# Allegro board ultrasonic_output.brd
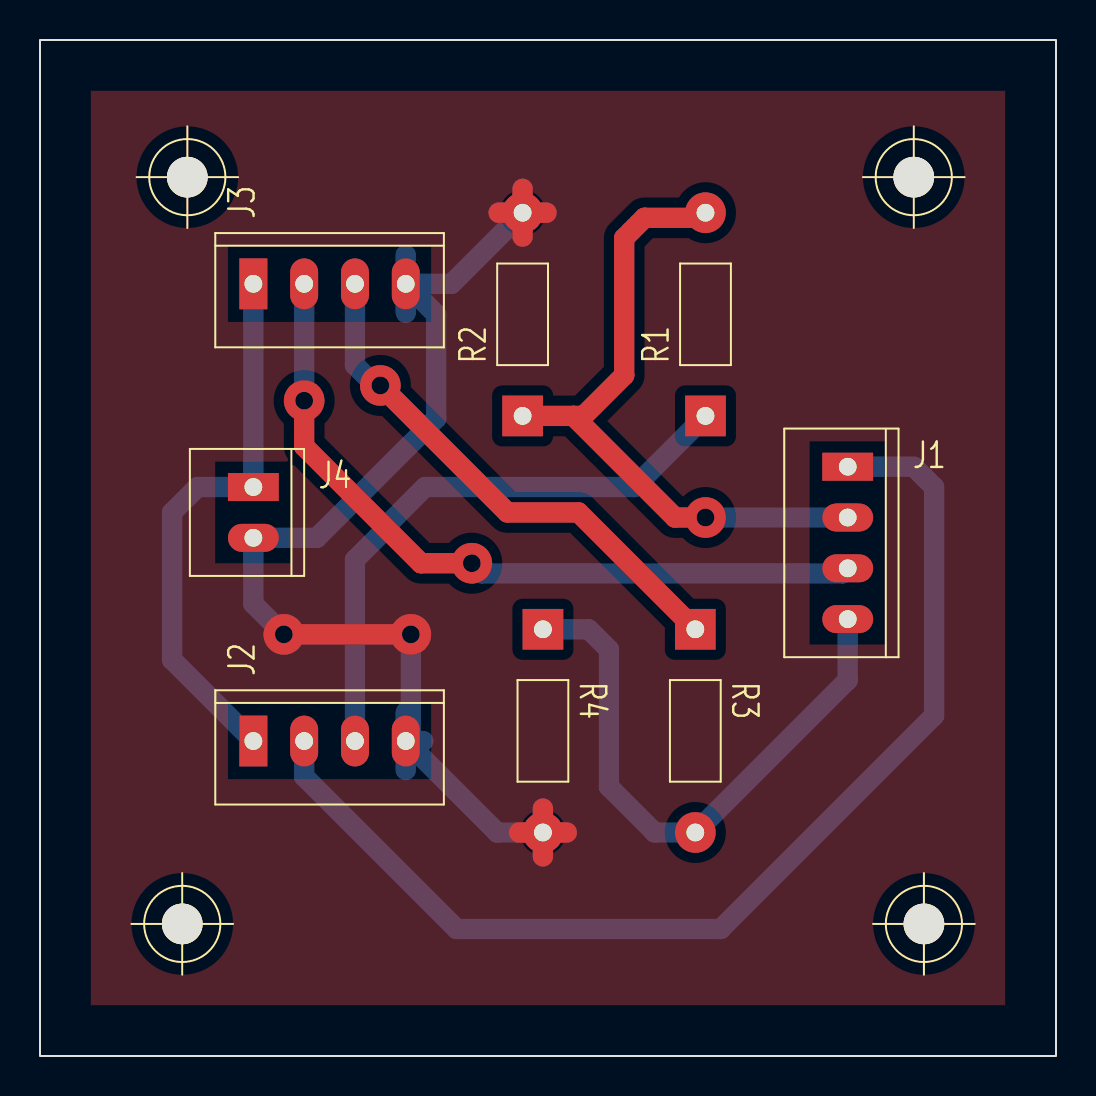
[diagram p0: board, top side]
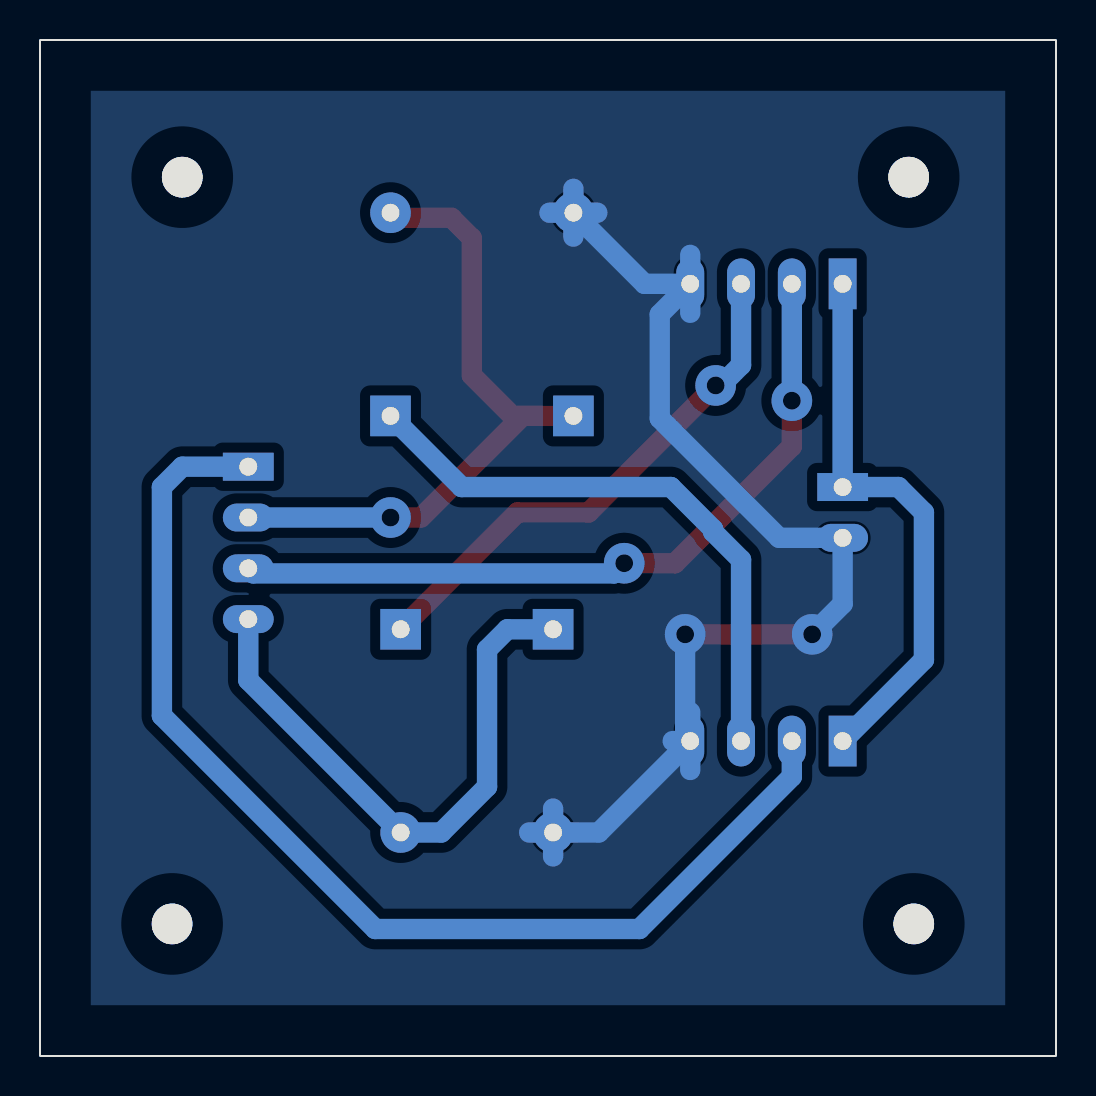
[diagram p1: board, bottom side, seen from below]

Outline 50.8 x 50.8 mm; copper layers: TOP, BOTTOM. Coordinates in mm from the lower left corner of the outline.
Outline path: rectangle 0,0 50.8,50.8

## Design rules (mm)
constraint set DEFAULT: min track width 1.016

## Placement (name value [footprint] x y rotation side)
J1  CON4  [GU-MOLEX4]  40.39 29.46 0 top
J2  CON4  [GU-MOLEX4]  10.67 15.75 90 top
J3  CON4  [GU-MOLEX4]  10.67 38.61 90 top
J4  CON2  [GU-MOLEX2]  10.67 28.45 0 top
NOREF  -  [unnamed]  44.2 6.6 0 top
NOREF#2  -  [unnamed]  7.11 6.6 0 top
NOREF#3  -  [unnamed]  7.37 43.94 0 top
NOREF#4  -  [unnamed]  43.69 43.94 0 top
R1  1k  [GU-RC400]  33.27 32 90 top
R2  2k  [GU-RC400]  24.13 32 90 top
R3  1k  [GU-RC400]  32.77 21.34 270 top
R4  2k  [GU-RC400]  25.15 21.34 270 top

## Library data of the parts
J1-J3 = CON4
J4 = CON2
R1-R4 = R

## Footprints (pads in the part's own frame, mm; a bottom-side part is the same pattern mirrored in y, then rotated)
GU-MOLEX2
  rect 2.54x1.397 hole 0.889: 1(0,0)
  oval 2.54x1.397 hole 0.889: 2(0,-2.54)
GU-MOLEX4
  rect 2.54x1.397 hole 0.889: 1(0,0)
  oval 2.54x1.397 hole 0.889: 2(0,-2.54) 3(0,-5.08) 4(0,-7.62)
GU-RC400
  rect 2.032x2.032 hole 0.889: 1(0,0)
  round 2.032 hole 0.889: 2(10.16,0)
unnamed
  round 2.032 hole 3.962 unplated: (0,0)

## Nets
5V: J2.1 J3.1 J4.1
GND: J2.4 J3.4 J4.2 R2.2 R4.2
N00132: J1.1 J2.2
N00136: J2.3 R1.1
N00189: J1.2 R1.2 R2.1
N00349: J1.3 J3.2
N00369: J3.3 R3.1
N00373: J1.4 R3.2 R4.1

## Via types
v1: diameter 2.032, hole 0.889, TOP to BOTTOM, 6 vias

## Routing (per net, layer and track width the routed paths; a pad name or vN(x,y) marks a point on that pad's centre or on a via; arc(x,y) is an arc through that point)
5V: length 27.9
  BOTTOM w1.016: J3.1 J4.1 7.87,28.45 6.6,27.18 6.6,19.81 J2.1
GND: length 76.9
  TOP w1.016: R2.2 25.32,42.16 ; R2.2 24.13,40.97 ; R2.2 22.94,42.16 ; R2.2 24.13,43.36 ; R4.2 26.34,11.18 ; R4.2 23.95,11.18 ; R4.2 25.15,12.37 ; R4.2 25.15,9.98 ; v1(12.19,21.08) v1(18.54,21.08)
  BOTTOM w1.016: 18.29,37.16 J3.4 ; J3.4 20.57,38.61 R2.2 ; J3.4 18.29,40.06 ; J3.4 19.81,37.08 19.81,31.88 13.84,25.91 J4.2 10.67,22.61 v1(12.19,21.08) ; R4.2 26.34,11.18 ; R4.2 25.15,9.98 ; R4.2 22.86,11.18 J2.4 ; R4.2 25.15,12.37 ; 18.29,14.3 J2.4 ; J2.4 18.54,16 v1(18.54,21.08) ; J2.4 19.16,15.75 ; J2.4 18.29,17.2 ; R2.2 24.13,43.36 ; R2.2 25.32,42.16 ; R2.2 22.94,42.16 ; R2.2 24.13,40.97
N00132: length 57
  BOTTOM w1.016: J2.2 13.21,13.97 20.83,6.35 34.04,6.35 44.7,17.02 44.7,28.45 43.69,29.46 J1.1
N00136: length 29.6
  BOTTOM w1.016: J2.3 15.75,24.81 17.14,26.21 17.14,26.34 19.25,28.45 29.72,28.45 R1.1
N00189: length 33.2
  TOP w1.016: 26.67,32 27.18,32 29.21,34.04 29.21,40.89 30.23,41.91 33.02,41.91 R1.2 ; 26.67,32 R2.1 ; 26.67,32 31.75,26.92 v1(33.27,26.92)
  BOTTOM w1.016: v1(33.27,26.92) J1.2
N00349: length 38
  TOP w1.016: v1(21.59,24.64) 19.05,24.64 13.21,30.48 v1(13.21,32.77)
  BOTTOM w1.016: J3.2 v1(13.21,32.77) ; J1.3 40.13,24.13 22.1,24.13 v1(21.59,24.64)
N00369: length 26.6
  TOP w1.016: v1(17.02,33.53) 23.37,27.18 26.92,27.18 R3.1
  BOTTOM w1.016: J3.3 15.75,34.54 16.76,33.53 v1(17.02,33.53)
N00373: length 29.7
  BOTTOM w1.016: J1.4 40.39,18.8 R3.2 30.73,11.18 28.45,13.46 28.45,20.32 27.43,21.34 R4.1

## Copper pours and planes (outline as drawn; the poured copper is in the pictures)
GND on TOP, BOTTOM: 2.54,48.26 48.26,48.26 48.26,2.54 2.54,2.54
